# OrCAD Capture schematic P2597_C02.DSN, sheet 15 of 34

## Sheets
15 19_ON OFF CONTROLLER: size Custom
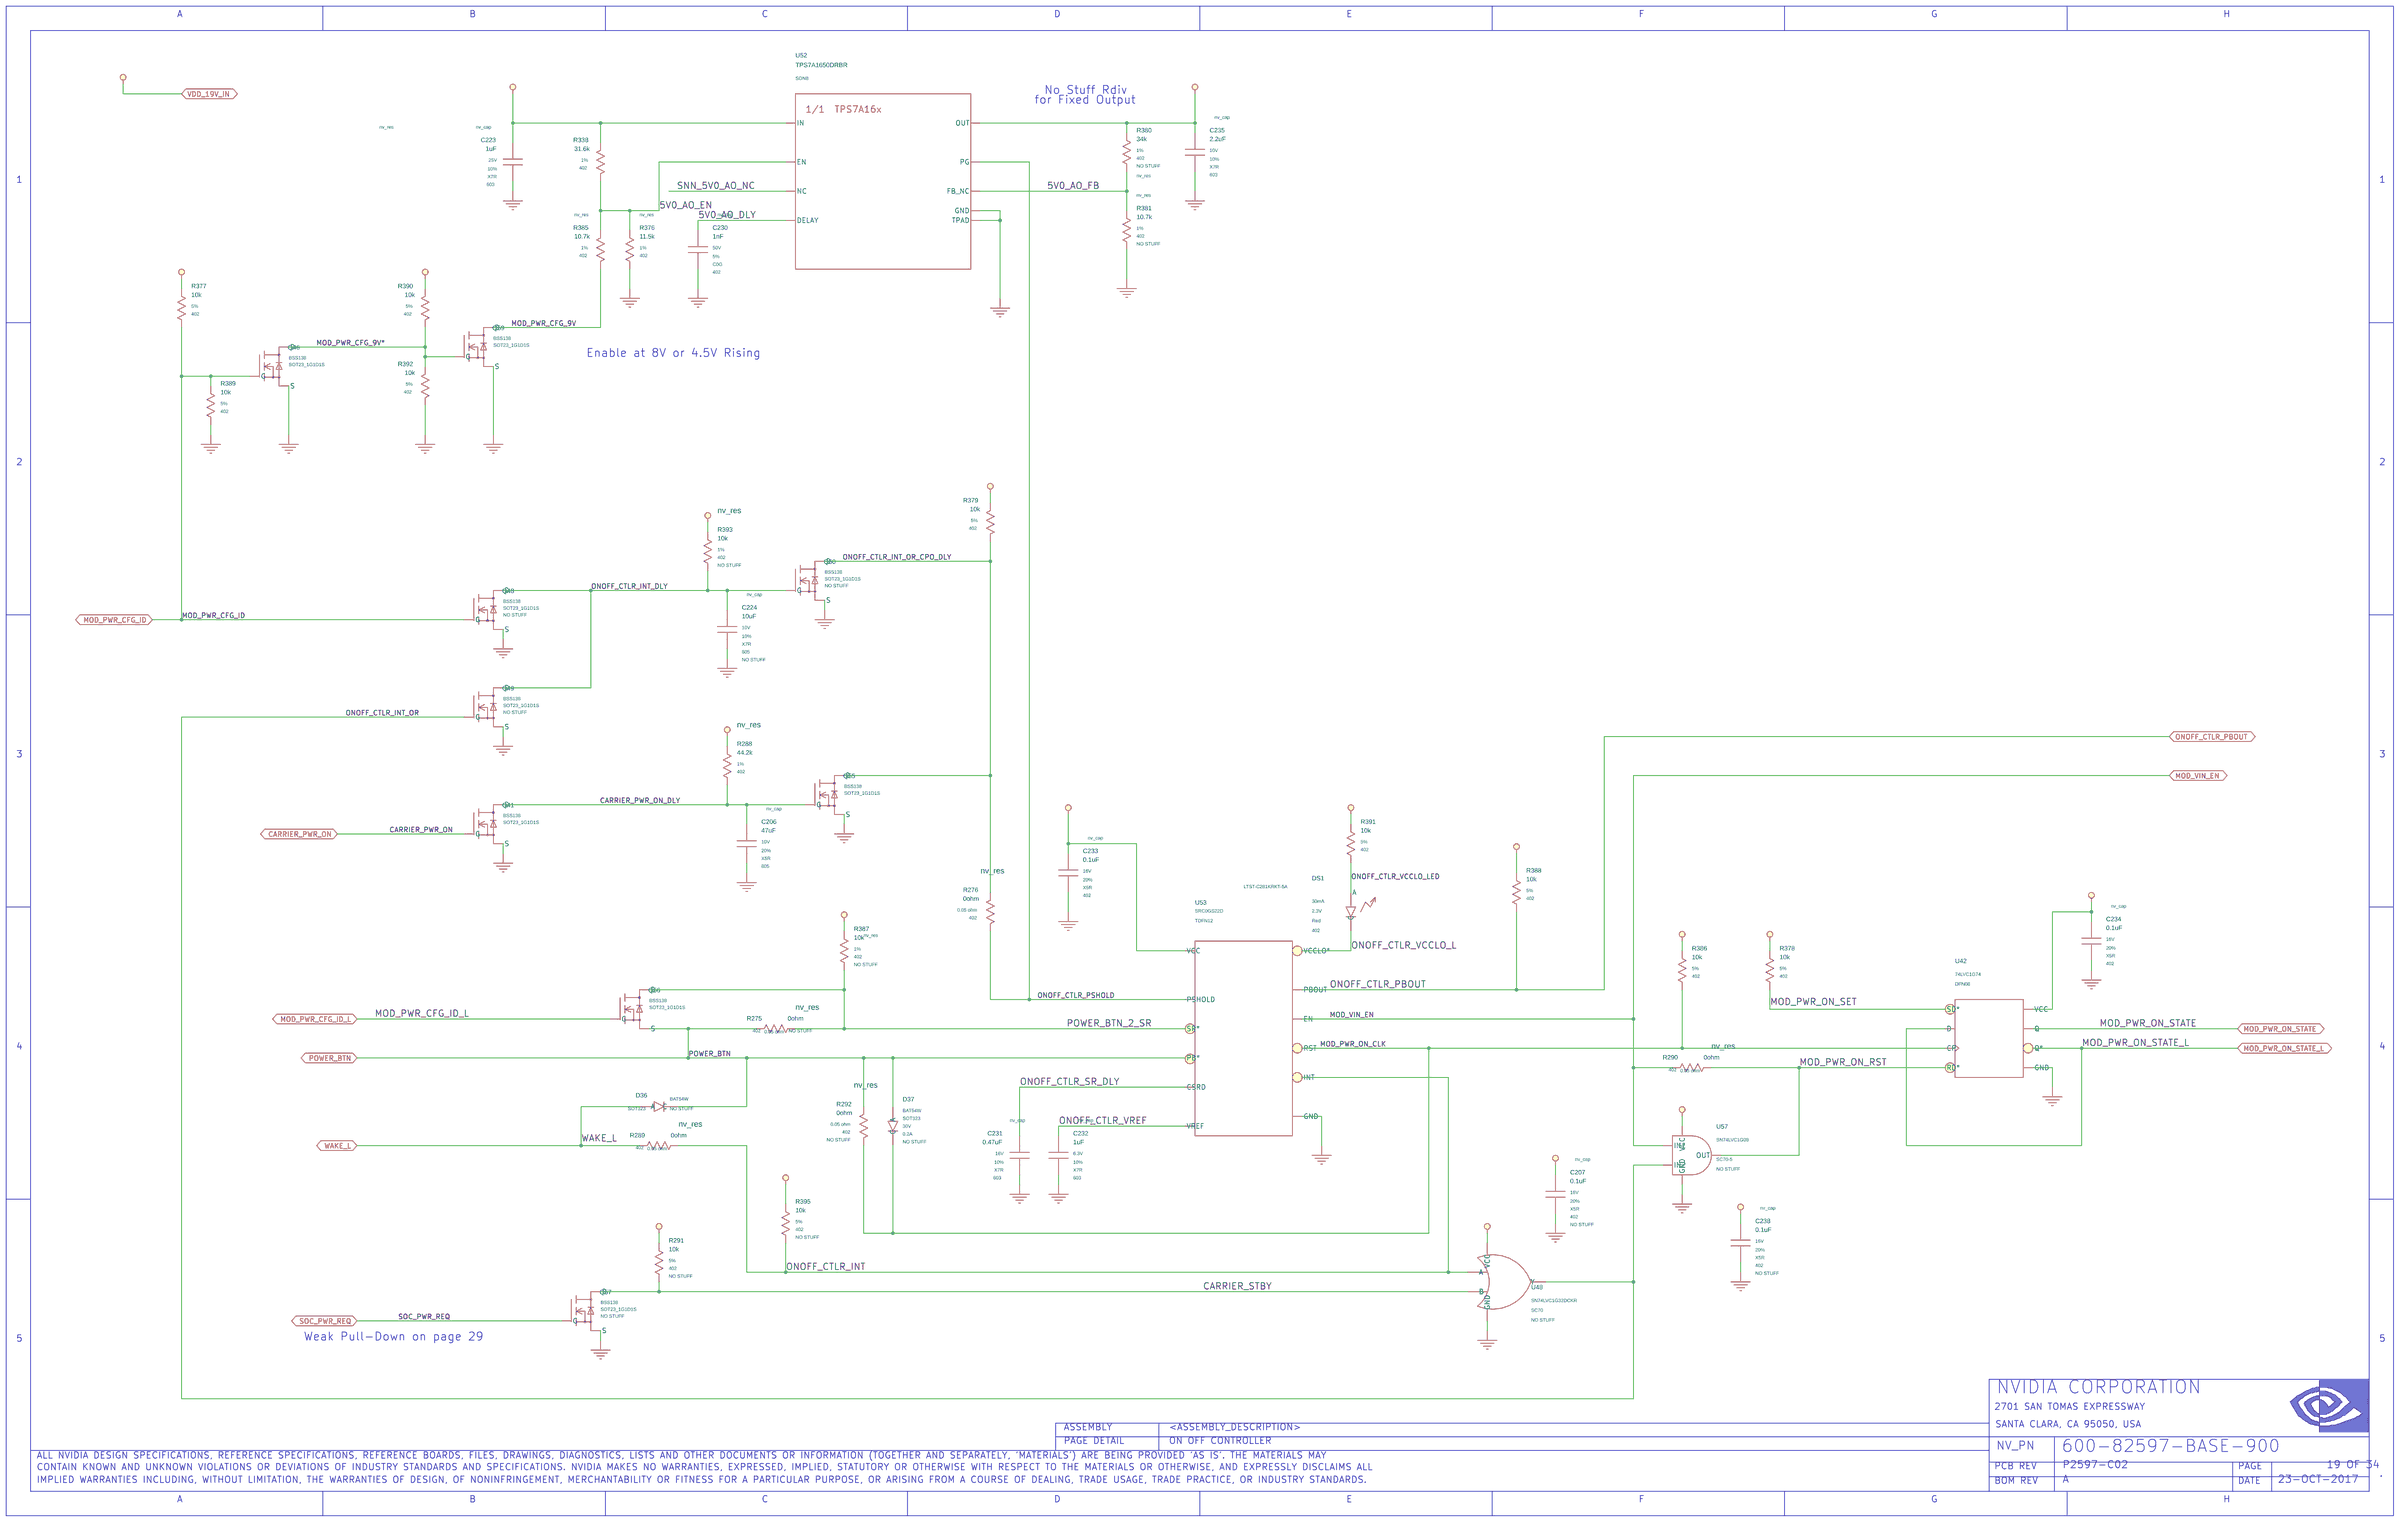
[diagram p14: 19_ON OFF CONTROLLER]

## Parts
C206  47uF  [805]
C207  0.1uF  [402]
C223  1uF  [603]
C224  10uF  [805]
C230  1nF  [402]
C231  0.47uF  [603]
C232  1uF  [603]
C233  0.1uF  [402]
C234  0.1uF  [402]
C235  2.2uF  [603]
C238  0.1uF  [402]
D36  D  [SOT323]
D37  D  [SOT323]
DS1  LED  [LED_SMD_0402_ST]
Q41  Q_FET_N_ENH  [SOT23]
Q46  Q_FET_N_ENH  [SOT23]
Q48  Q_FET_N_ENH  [SOT23]
Q49  Q_FET_N_ENH  [SOT23]
Q55  Q_FET_N_ENH  [SOT23]
Q56  Q_FET_N_ENH  [SOT23]
Q57  Q_FET_N_ENH  [SOT23]
Q59  Q_FET_N_ENH  [SOT23]
Q60  Q_FET_N_ENH  [SOT23]
R275  0ohm  [402]
R276  0ohm  [402]
R288  44.2k  [402]
R289  0ohm  [402]
R290  0ohm  [402]
R291  10k  [402]
R292  0ohm  [402]
R338  31.6k  [402]
R376  11.5k  [402]
R377  10k  [402]
R378  10k  [402]
R379  10k  [402]
R380  34k  [402]
R381  10.7k  [402]
R385  10.7k  [402]
R386  10k  [402]
R387  10k  [402]
R388  10k  [402]
R389  10k  [402]
R390  10k  [402]
R391  10k  [402]
R392  10k  [402]
R393  10k  [402]
R395  10k  [402]
U42  U_FLIPFLOP_D  [DFN08_P050_020X010]
U48  U_OR_2IN  [SC70_5]
U52  1.2V  [SON08_030X030_T025X017]
U53  U_PB_SRC0XXX  [DFN12_P050_030X020]
U57  U_AND_2IN  [SC70_5]

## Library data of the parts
C206 = C: ASSEMBLY: ON_OFF_CTRL; CDS_LIB: discrete; CDS_PART_NAME: C_0805-47UF,X5R,20%,10V,032-0775-000; CDS_PHYS_PART_NAME: C_0805-47UF,X5R,20%,10V,032-0775-000-032-0775-000,47UF; CDS_SEC: 1; DEVICE_TYPENAME: C_0805-47UFX5R2010V032-0775-000-032-0775-00047UF; DRAWING: @P2597_C02_LIB.P2597_C02(SCH_1):PAGE19; MAT: X5R; MAX_VOLTAGE: 10V; NV_PN: 032-0775-000; PATH: I158; PHYS_PAGE: 19; ROT: 0; SEC: 1; SIGNAL_MODEL: nv_cap; TOL: 20%; VER: 1; XY: (-8350,3300)
C207 = C: ASSEMBLY: ON_OFF_CTRL_INT_OFF; CDS_LIB: discrete; CDS_PART_NAME: C_0402-0.1UF,X5R,20%,16V,032-0877-000; CDS_PHYS_PART_NAME: C_0402-0.1UF,X5R,20%,16V,032-0877-000-0.1UF,032-0877-000; CDS_SEC: 1; DEVICE_TYPENAME: C_0402-01UFX5R2016V032-0877-000-01UF032-0877-000; DRAWING: @P2597_C02_LIB.P2597_C02(SCH_1):PAGE19; MAT: X5R; MAX_VOLTAGE: 16V; NV_PN: 032-0877-000; PATH: I163; PHYS_PAGE: 19; ROT: 0; SEC: 1; SIGNAL_MODEL: nv_cap; SKU: NO STUFF; TOL: 20%; VER: 1; XY: (-4200,1500)
C223 = C: ASSEMBLY: ON_OFF_CTRL; CDS_LIB: discrete; CDS_PART_NAME: C_0603-1UF,X7R,10%,25V,032-0686-000; CDS_PHYS_PART_NAME: C_0603-1UF,X7R,10%,25V,032-0686-000-032-0686-000,1UF; CDS_SEC: 1; DEVICE_TYPENAME: C_0603-1UFX7R1025V032-0686-000-032-0686-0001UF; DRAWING: @P2597_C02_LIB.P2597_C02(SCH_1):PAGE19; MAT: X7R; MAX_VOLTAGE: 25V; NV_PN: 032-0686-000; PATH: I109; PHYS_PAGE: 19; ROT: 2; SEC: 1; SIGNAL_MODEL: nv_cap; TOL: 10%; VER: 1; XY: (-9550,6800)
C224 = C: ASSEMBLY: ON_OFF_CTRL_INT_OFF; CDS_LIB: discrete; CDS_PART_NAME: C_0805-10UF,X7R,10%,10V,032-0462-000; CDS_PHYS_PART_NAME: C_0805-10UF,X7R,10%,10V,032-0462-000-032-0462-000,10UF; CDS_SEC: 1; DEVICE_TYPENAME: C_0805-10UFX7R1010V032-0462-000-032-0462-00010UF; DRAWING: @P2597_C02_LIB.P2597_C02(SCH_1):PAGE19; MAT: X7R; MAX_VOLTAGE: 10V; NV_PN: 032-0462-000; PATH: I133; PHYS_PAGE: 19; ROT: 0; SEC: 1; SIGNAL_MODEL: nv_cap; SKU: NO STUFF; TOL: 10%; VER: 1; XY: (-8450,4400)
C230 = C: ASSEMBLY: ON_OFF_CTRL; CDS_LIB: discrete; CDS_PART_NAME: C_0402-1NF,C0G,5%,50V,035-0298-000; CDS_PHYS_PART_NAME: C_0402-1NF,C0G,5%,50V,035-0298-000-035-0298-000,1NF; CDS_SEC: 1; DEVICE_TYPENAME: C_0402-1NFC0G550V035-0298-000-035-0298-0001NF; DRAWING: @P2597_C02_LIB.P2597_C02(SCH_1):PAGE19; MAT: C0G; MAX_VOLTAGE: 50V; NV_PN: 035-0298-000; PATH: I101; PHYS_PAGE: 19; ROT: 0; SEC: 1; SIGNAL_MODEL: nv_cap; TOL: 5%; VER: 1; XY: (-8600,6350)
C231 = C: ASSEMBLY: ON_OFF_CTRL; CDS_LIB: discrete; CDS_PART_NAME: C_0603-0.47UF,X7R,10%,16V,036-0040-000; CDS_PHYS_PART_NAME: C_0603-0.47UF,X7R,10%,16V,036-0040-000-0.47UF,036-0040-000; CDS_SEC: 1; DEVICE_TYPENAME: C_0603-047UFX7R1016V036-0040-000-047UF036-0040-000; DRAWING: @P2597_C02_LIB.P2597_C02(SCH_1):PAGE19; MAT: X7R; MAX_VOLTAGE: 16V; NV_PN: 036-0040-000; PATH: I138; PHYS_PAGE: 19; ROT: 2; SEC: 1; SIGNAL_MODEL: nv_cap; TOL: 10%; VER: 1; XY: (-6950,1700)
C232 = C: ASSEMBLY: ON_OFF_CTRL; CDS_LIB: discrete; CDS_PART_NAME: C_0603-1UF,X7R,10%,6.3V,036-0027-000; CDS_PHYS_PART_NAME: C_0603-1UF,X7R,10%,6.3V,036-0027-000-036-0027-000,1UF; CDS_SEC: 1; DEVICE_TYPENAME: C_0603-1UFX7R1063V036-0027-000-036-0027-0001UF; DRAWING: @P2597_C02_LIB.P2597_C02(SCH_1):PAGE19; MAT: X7R; MAX_VOLTAGE: 6.3V; NV_PN: 036-0027-000; PATH: I103; PHYS_PAGE: 19; ROT: 0; SEC: 1; SIGNAL_MODEL: nv_cap; TOL: 10%; VER: 1; XY: (-6750,1700)
C233 = C: ASSEMBLY: ON_OFF_CTRL; CDS_LIB: discrete; CDS_PART_NAME: C_0402-0.1UF,X5R,20%,16V,032-0877-000; CDS_PHYS_PART_NAME: C_0402-0.1UF,X5R,20%,16V,032-0877-000-0.1UF,032-0877-000; CDS_SEC: 1; DEVICE_TYPENAME: C_0402-01UFX5R2016V032-0877-000-01UF032-0877-000; DRAWING: @P2597_C02_LIB.P2597_C02(SCH_1):PAGE19; MAT: X5R; MAX_VOLTAGE: 16V; NV_PN: 032-0877-000; PATH: I95; PHYS_PAGE: 19; ROT: 0; SEC: 1; SIGNAL_MODEL: nv_cap; TOL: 20%; VER: 1; XY: (-6700,3150)
C234 = C: ASSEMBLY: ON_OFF_CTRL; CDS_LIB: discrete; CDS_PART_NAME: C_0402-0.1UF,X5R,20%,16V,032-0877-000; CDS_PHYS_PART_NAME: C_0402-0.1UF,X5R,20%,16V,032-0877-000-0.1UF,032-0877-000; CDS_SEC: 1; DEVICE_TYPENAME: C_0402-01UFX5R2016V032-0877-000-01UF032-0877-000; DRAWING: @P2597_C02_LIB.P2597_C02(SCH_1):PAGE19; MAT: X5R; MAX_VOLTAGE: 16V; NV_PN: 032-0877-000; PATH: I48; PHYS_PAGE: 19; ROT: 0; SEC: 1; SIGNAL_MODEL: nv_cap; TOL: 20%; VER: 1; XY: (-1450,2800)
C235 = C: ASSEMBLY: ON_OFF_CTRL; CDS_LIB: discrete; CDS_PART_NAME: C_0603-2.2UF,X7R,10%,10V,036-0219-000; CDS_PHYS_PART_NAME: C_0603-2.2UF,X7R,10%,10V,036-0219-000-036-0219-000,2.2UF; CDS_SEC: 1; DEVICE_TYPENAME: C_0603-22UFX7R1010V036-0219-000-036-0219-00022UF; DRAWING: @P2597_C02_LIB.P2597_C02(SCH_1):PAGE19; MAT: X7R; MAX_VOLTAGE: 10V; NV_PN: 036-0219-000; PATH: I67; PHYS_PAGE: 19; ROT: 0; SEC: 1; SIGNAL_MODEL: nv_cap; TOL: 10%; VER: 1; XY: (-6050,6850)
C238 = C: ASSEMBLY: ON_OFF_CTRL_INT_OFF; CDS_LIB: discrete; CDS_PART_NAME: C_0402-0.1UF,X5R,20%,16V,032-0877-000; CDS_PHYS_PART_NAME: C_0402-0.1UF,X5R,20%,16V,032-0877-000-0.1UF,032-0877-000; CDS_SEC: 1; DEVICE_TYPENAME: C_0402-01UFX5R2016V032-0877-000-01UF032-0877-000; DRAWING: @P2597_C02_LIB.P2597_C02(SCH_1):PAGE19; MAT: X5R; MAX_VOLTAGE: 16V; NV_PN: 032-0877-000; PATH: I88; PHYS_PAGE: 19; ROT: 0; SEC: 1; SIGNAL_MODEL: nv_cap; SKU: NO STUFF; TOL: 20%; VER: 1; XY: (-3250,1250)
D36 = D: ASSEMBLY: ON_OFF_CTRL_PB2WAKE; CDS_LIB: discrete; CDS_PART_NAME: D_SOT323-BAT54W,SINGLE,30V,0.6A,1V@0.1A,0.2A,090-0106-000; CDS_PHYS_PART_NAME: D_SOT323-BAT54W,SINGLE,30V,0.6A,1V@0.1A,0.2A,090-0106-000-090-0106-000; CDS_SEC: 1; CONFIGURATION: Single; CONTINUOUS_CURRENT: 0.2A; DEVICE_TYPENAME: D_SOT323-BAT54WSINGLE30V06A1V01A02A090-0106-000-090-0106-000; DRAWING: @P2597_C02_LIB.P2597_C02(SCH_1):PAGE19; FORWARD_VOLTAGE: 1V@0.1A; MAX_CURRENT: 0.6A; MAX_VOLTAGE: 30V; NV_NAME: BAT54W; NV_PN: 090-0106-000; PATH: I174; PHYS_PAGE: 19; ROT: 0; SEC: 1; SKU: NO STUFF; VER: 3; XY: (-8800,1950)
D37 = D#1: ASSEMBLY: ON_OFF_CTRL_RST2PB; CDS_LIB: discrete; CDS_PART_NAME: D_SOT323-BAT54W,SINGLE,30V,0.6A,1V@0.1A,0.2A,090-0106-000; CDS_PHYS_PART_NAME: D_SOT323-BAT54W,SINGLE,30V,0.6A,1V@0.1A,0.2A,090-0106-000-090-0106-000; CDS_SEC: 1; CONFIGURATION: Single; CONTINUOUS_CURRENT: 0.2A; DEVICE_TYPENAME: D_SOT323-BAT54WSINGLE30V06A1V01A02A090-0106-000-090-0106-000; DRAWING: @P2597_C02_LIB.P2597_C02(SCH_1):PAGE19; FORWARD_VOLTAGE: 1V@0.1A; MAX_CURRENT: 0.6A; MAX_VOLTAGE: 30V; NV_NAME: BAT54W; NV_PN: 090-0106-000; PATH: I184; PHYS_PAGE: 19; ROT: 0; SEC: 1; SKU: NO STUFF; VER: 1; XY: (-7600,1850)
DS1 = LED: ASSEMBLY: ON_OFF_CTRL_VCCLO_LED; CDS_LIB: discrete; CDS_PART_NAME: LED_0402-LTST-C281KRKT-5A,5V,80MA,2.3V,30MA,RED,092-0090-000; CDS_PHYS_PART_NAME: LED_0402-LTST-C281KRKT-5A,5V,80MA,2.3V,30MA,RED,092-0090-000-092-0090-000; CDS_SEC: 1; CONTINUOUS_CURRENT: 30mA; DEVICE_TYPENAME: LED_0402-LTST-C281KRKT-5A5V80MA23V30MARED092-0090-000-092-0090-000; DRAWING: @P2597_C02_LIB.P2597_C02(SCH_1):PAGE19; FORWARD_VOLTAGE: 2.3V; MAX_CURRENT: 80mA; MAX_VOLTAGE: 5V; NV_COLOR: Red; NV_NAME: LTST-C281KRKT-5A; NV_PN: 092-0090-000; PACK_TYPE: 402; PATH: I93; PHYS_PAGE: 19; ROT: 0; SEC: 1; VER: 1; XY: (-5250,2950)
Q41 = Q_FET_N_ENH#2: ASSEMBLY: ON_OFF_CTRL; CDS_LIB: discrete; CDS_PART_NAME: Q_FET_N_ENH_SOT23_1G1D1S-BSS138,50V,3500MOHM@10V / 3500MOHM@4.5V / 3500MOHM@2.5V,0.2A,0.2A,20V,0.3W,[ ]@10V / [ ]@4.5V / [ ]@2A; CDS_PHYS_PART_NAME: Q_FET_N_ENH_SOT23_1G1D1S-BSS138,50V,3500MOHM@10V / 3500MOHM@4.5V / 3500MOHM@2.5V,0.2A,0.2A,20V,0.3W,[ ]@10V / [ ]@4.5V / [ ]@2B; CDS_SEC: 1; CONTINUOUS_CURRENT: 0.2A; CaptureCellPackProp: Q_FET_N_ENH__sym_2##2; DEVICE_TYPENAME: Q_FET_N_ENH_SOT23_1G1D1S-BSS13850V3500MOHM10V3500MOHM45V3500MOHM25V02A02A20V03W10V45V2B; DRAWING: @P2597_C02_LIB.P2597_C02(SCH_1):PAGE19; MAX_CURRENT: 0.2A; MAX_VOLTAGE: 50V; MAX_WATTAGE: 0.3W; NV_NAME: BSS138; NV_PN: 300-0156-000; PACK_TYPE: SOT23_1G1D1S; PATH: I143; PHYS_PAGE: 19; Q_G: [ ]@10V / [ ]@4.5V / [ ]@2.5V; ROT: 0; R_DS_ON: 3500mohm@10V / 3500mohm@4.5V / 3500mohm@2.5V; SEC: 1; VER: 2; V_BE_GS: 20V; XY: (-9700,3400)
Q46 = Q_FET_N_ENH#2: ASSEMBLY: ON_OFF_CTRL; CDS_LIB: discrete; CDS_PART_NAME: Q_FET_N_ENH_SOT23_1G1D1S-BSS138,50V,3500MOHM@10V / 3500MOHM@4.5V / 3500MOHM@2.5V,0.2A,0.2A,20V,0.3W,[ ]@10V / [ ]@4.5V / [ ]@2A; CDS_PHYS_PART_NAME: Q_FET_N_ENH_SOT23_1G1D1S-BSS138,50V,3500MOHM@10V / 3500MOHM@4.5V / 3500MOHM@2.5V,0.2A,0.2A,20V,0.3W,[ ]@10V / [ ]@4.5V / [ ]@2B; CDS_SEC: 1; CONTINUOUS_CURRENT: 0.2A; CaptureCellPackProp: Q_FET_N_ENH__sym_2##2; DEVICE_TYPENAME: Q_FET_N_ENH_SOT23_1G1D1S-BSS13850V3500MOHM10V3500MOHM45V3500MOHM25V02A02A20V03W10V45V2B; DRAWING: @P2597_C02_LIB.P2597_C02(SCH_1):PAGE19; MAX_CURRENT: 0.2A; MAX_VOLTAGE: 50V; MAX_WATTAGE: 0.3W; NV_NAME: BSS138; NV_PN: 300-0156-000; PACK_TYPE: SOT23_1G1D1S; PATH: I121; PHYS_PAGE: 19; Q_G: [ ]@10V / [ ]@4.5V / [ ]@2.5V; ROT: 0; R_DS_ON: 3500mohm@10V / 3500mohm@4.5V / 3500mohm@2.5V; SEC: 1; VER: 2; V_BE_GS: 20V; XY: (-10800,5750)
Q48 = Q_FET_N_ENH#2: ASSEMBLY: ON_OFF_CTRL_INT_OFF; CDS_LIB: discrete; CDS_PART_NAME: Q_FET_N_ENH_SOT23_1G1D1S-BSS138,50V,3500MOHM@10V / 3500MOHM@4.5V / 3500MOHM@2.5V,0.2A,0.2A,20V,0.3W,[ ]@10V / [ ]@4.5V / [ ]@2A; CDS_PHYS_PART_NAME: Q_FET_N_ENH_SOT23_1G1D1S-BSS138,50V,3500MOHM@10V / 3500MOHM@4.5V / 3500MOHM@2.5V,0.2A,0.2A,20V,0.3W,[ ]@10V / [ ]@4.5V / [ ]@2B; CDS_SEC: 1; CONTINUOUS_CURRENT: 0.2A; CaptureCellPackProp: Q_FET_N_ENH__sym_2##2; DEVICE_TYPENAME: Q_FET_N_ENH_SOT23_1G1D1S-BSS13850V3500MOHM10V3500MOHM45V3500MOHM25V02A02A20V03W10V45V2B; DRAWING: @P2597_C02_LIB.P2597_C02(SCH_1):PAGE19; MAX_CURRENT: 0.2A; MAX_VOLTAGE: 50V; MAX_WATTAGE: 0.3W; NV_NAME: BSS138; NV_PN: 300-0156-000; PACK_TYPE: SOT23_1G1D1S; PATH: I141; PHYS_PAGE: 19; Q_G: [ ]@10V / [ ]@4.5V / [ ]@2.5V; ROT: 0; R_DS_ON: 3500mohm@10V / 3500mohm@4.5V / 3500mohm@2.5V; SEC: 1; SKU: NO STUFF; VER: 2; V_BE_GS: 20V; XY: (-9700,4500)
Q49 = Q_FET_N_ENH#2: ASSEMBLY: ON_OFF_CTRL_INT_OFF; CDS_LIB: discrete; CDS_PART_NAME: Q_FET_N_ENH_SOT23_1G1D1S-BSS138,50V,3500MOHM@10V / 3500MOHM@4.5V / 3500MOHM@2.5V,0.2A,0.2A,20V,0.3W,[ ]@10V / [ ]@4.5V / [ ]@2A; CDS_PHYS_PART_NAME: Q_FET_N_ENH_SOT23_1G1D1S-BSS138,50V,3500MOHM@10V / 3500MOHM@4.5V / 3500MOHM@2.5V,0.2A,0.2A,20V,0.3W,[ ]@10V / [ ]@4.5V / [ ]@2B; CDS_SEC: 1; CONTINUOUS_CURRENT: 0.2A; CaptureCellPackProp: Q_FET_N_ENH__sym_2##2; DEVICE_TYPENAME: Q_FET_N_ENH_SOT23_1G1D1S-BSS13850V3500MOHM10V3500MOHM45V3500MOHM25V02A02A20V03W10V45V2B; DRAWING: @P2597_C02_LIB.P2597_C02(SCH_1):PAGE19; MAX_CURRENT: 0.2A; MAX_VOLTAGE: 50V; MAX_WATTAGE: 0.3W; NV_NAME: BSS138; NV_PN: 300-0156-000; PACK_TYPE: SOT23_1G1D1S; PATH: I144; PHYS_PAGE: 19; Q_G: [ ]@10V / [ ]@4.5V / [ ]@2.5V; ROT: 0; R_DS_ON: 3500mohm@10V / 3500mohm@4.5V / 3500mohm@2.5V; SEC: 1; SKU: NO STUFF; VER: 2; V_BE_GS: 20V; XY: (-9700,4000)
Q55 = Q_FET_N_ENH#2: ASSEMBLY: ON_OFF_CTRL; CDS_LIB: discrete; CDS_PART_NAME: Q_FET_N_ENH_SOT23_1G1D1S-BSS138,50V,3500MOHM@10V / 3500MOHM@4.5V / 3500MOHM@2.5V,0.2A,0.2A,20V,0.3W,[ ]@10V / [ ]@4.5V / [ ]@2A; CDS_PHYS_PART_NAME: Q_FET_N_ENH_SOT23_1G1D1S-BSS138,50V,3500MOHM@10V / 3500MOHM@4.5V / 3500MOHM@2.5V,0.2A,0.2A,20V,0.3W,[ ]@10V / [ ]@4.5V / [ ]@2B; CDS_SEC: 1; CONTINUOUS_CURRENT: 0.2A; CaptureCellPackProp: Q_FET_N_ENH__sym_2##2; DEVICE_TYPENAME: Q_FET_N_ENH_SOT23_1G1D1S-BSS13850V3500MOHM10V3500MOHM45V3500MOHM25V02A02A20V03W10V45V2B; DRAWING: @P2597_C02_LIB.P2597_C02(SCH_1):PAGE19; MAX_CURRENT: 0.2A; MAX_VOLTAGE: 50V; MAX_WATTAGE: 0.3W; NV_NAME: BSS138; NV_PN: 300-0156-000; PACK_TYPE: SOT23_1G1D1S; PATH: I161; PHYS_PAGE: 19; Q_G: [ ]@10V / [ ]@4.5V / [ ]@2.5V; ROT: 0; R_DS_ON: 3500mohm@10V / 3500mohm@4.5V / 3500mohm@2.5V; SEC: 1; VER: 2; V_BE_GS: 20V; XY: (-7950,3550)
Q56 = Q_FET_N_ENH#2: ASSEMBLY: ON_OFF_CTRL_PB2SR_SMPL; CDS_LIB: discrete; CDS_PART_NAME: Q_FET_N_ENH_SOT23_1G1D1S-BSS138,50V,3500MOHM@10V / 3500MOHM@4.5V / 3500MOHM@2.5V,0.2A,0.2A,20V,0.3W,[ ]@10V / [ ]@4.5V / [ ]@2A; CDS_PHYS_PART_NAME: Q_FET_N_ENH_SOT23_1G1D1S-BSS138,50V,3500MOHM@10V / 3500MOHM@4.5V / 3500MOHM@2.5V,0.2A,0.2A,20V,0.3W,[ ]@10V / [ ]@4.5V / [ ]@2B; CDS_SEC: 1; CONTINUOUS_CURRENT: 0.2A; CaptureCellPackProp: Q_FET_N_ENH__sym_2##2; DEVICE_TYPENAME: Q_FET_N_ENH_SOT23_1G1D1S-BSS13850V3500MOHM10V3500MOHM45V3500MOHM25V02A02A20V03W10V45V2B; DRAWING: @P2597_C02_LIB.P2597_C02(SCH_1):PAGE19; MAX_CURRENT: 0.2A; MAX_VOLTAGE: 50V; MAX_WATTAGE: 0.3W; NV_NAME: BSS138; NV_PN: 300-0156-000; PACK_TYPE: SOT23_1G1D1S; PATH: I176; PHYS_PAGE: 19; Q_G: [ ]@10V / [ ]@4.5V / [ ]@2.5V; ROT: 0; R_DS_ON: 3500mohm@10V / 3500mohm@4.5V / 3500mohm@2.5V; SEC: 1; VER: 2; V_BE_GS: 20V; XY: (-8950,2450)
Q57 = Q_FET_N_ENH#2: ASSEMBLY: ON_OFF_CTRL_INT_OFF; CDS_LIB: discrete; CDS_PART_NAME: Q_FET_N_ENH_SOT23_1G1D1S-BSS138,50V,3500MOHM@10V / 3500MOHM@4.5V / 3500MOHM@2.5V,0.2A,0.2A,20V,0.3W,[ ]@10V / [ ]@4.5V / [ ]@2A; CDS_PHYS_PART_NAME: Q_FET_N_ENH_SOT23_1G1D1S-BSS138,50V,3500MOHM@10V / 3500MOHM@4.5V / 3500MOHM@2.5V,0.2A,0.2A,20V,0.3W,[ ]@10V / [ ]@4.5V / [ ]@2B; CDS_SEC: 1; CONTINUOUS_CURRENT: 0.2A; CaptureCellPackProp: Q_FET_N_ENH__sym_2##2; DEVICE_TYPENAME: Q_FET_N_ENH_SOT23_1G1D1S-BSS13850V3500MOHM10V3500MOHM45V3500MOHM25V02A02A20V03W10V45V2B; DRAWING: @P2597_C02_LIB.P2597_C02(SCH_1):PAGE19; MAX_CURRENT: 0.2A; MAX_VOLTAGE: 50V; MAX_WATTAGE: 0.3W; NV_NAME: BSS138; NV_PN: 300-0156-000; PACK_TYPE: SOT23_1G1D1S; PATH: I183; PHYS_PAGE: 19; Q_G: [ ]@10V / [ ]@4.5V / [ ]@2.5V; ROT: 0; R_DS_ON: 3500mohm@10V / 3500mohm@4.5V / 3500mohm@2.5V; SEC: 1; SKU: NO STUFF; VER: 2; V_BE_GS: 20V; XY: (-9200,900)
Q59 = Q_FET_N_ENH#2: ASSEMBLY: ON_OFF_CTRL; CDS_LIB: discrete; CDS_PART_NAME: Q_FET_N_ENH_SOT23_1G1D1S-BSS138,50V,3500MOHM@10V / 3500MOHM@4.5V / 3500MOHM@2.5V,0.2A,0.2A,20V,0.3W,[ ]@10V / [ ]@4.5V / [ ]@2A; CDS_PHYS_PART_NAME: Q_FET_N_ENH_SOT23_1G1D1S-BSS138,50V,3500MOHM@10V / 3500MOHM@4.5V / 3500MOHM@2.5V,0.2A,0.2A,20V,0.3W,[ ]@10V / [ ]@4.5V / [ ]@2B; CDS_SEC: 1; CONTINUOUS_CURRENT: 0.2A; CaptureCellPackProp: Q_FET_N_ENH__sym_2##2; DEVICE_TYPENAME: Q_FET_N_ENH_SOT23_1G1D1S-BSS13850V3500MOHM10V3500MOHM45V3500MOHM25V02A02A20V03W10V45V2B; DRAWING: @P2597_C02_LIB.P2597_C02(SCH_1):PAGE19; MAX_CURRENT: 0.2A; MAX_VOLTAGE: 50V; MAX_WATTAGE: 0.3W; NV_NAME: BSS138; NV_PN: 300-0156-000; PACK_TYPE: SOT23_1G1D1S; PATH: I115; PHYS_PAGE: 19; Q_G: [ ]@10V / [ ]@4.5V / [ ]@2.5V; ROT: 0; R_DS_ON: 3500mohm@10V / 3500mohm@4.5V / 3500mohm@2.5V; SEC: 1; VER: 2; V_BE_GS: 20V; XY: (-9750,5850)
Q60 = Q_FET_N_ENH#2: ASSEMBLY: ON_OFF_CTRL_INT_OFF; CDS_LIB: discrete; CDS_PART_NAME: Q_FET_N_ENH_SOT23_1G1D1S-BSS138,50V,3500MOHM@10V / 3500MOHM@4.5V / 3500MOHM@2.5V,0.2A,0.2A,20V,0.3W,[ ]@10V / [ ]@4.5V / [ ]@2A; CDS_PHYS_PART_NAME: Q_FET_N_ENH_SOT23_1G1D1S-BSS138,50V,3500MOHM@10V / 3500MOHM@4.5V / 3500MOHM@2.5V,0.2A,0.2A,20V,0.3W,[ ]@10V / [ ]@4.5V / [ ]@2B; CDS_SEC: 1; CONTINUOUS_CURRENT: 0.2A; CaptureCellPackProp: Q_FET_N_ENH__sym_2##2; DEVICE_TYPENAME: Q_FET_N_ENH_SOT23_1G1D1S-BSS13850V3500MOHM10V3500MOHM45V3500MOHM25V02A02A20V03W10V45V2B; DRAWING: @P2597_C02_LIB.P2597_C02(SCH_1):PAGE19; MAX_CURRENT: 0.2A; MAX_VOLTAGE: 50V; MAX_WATTAGE: 0.3W; NV_NAME: BSS138; NV_PN: 300-0156-000; PACK_TYPE: SOT23_1G1D1S; PATH: I128; PHYS_PAGE: 19; Q_G: [ ]@10V / [ ]@4.5V / [ ]@2.5V; ROT: 0; R_DS_ON: 3500mohm@10V / 3500mohm@4.5V / 3500mohm@2.5V; SEC: 1; SKU: NO STUFF; VER: 2; V_BE_GS: 20V; XY: (-8050,4650)
R275 = R: ASSEMBLY: ON_OFF_CTRL_PB2SR_SMPL; CDS_LIB: discrete; CDS_PART_NAME: R_0402-0OHM,0.05 OHM,62.5MW,195-2655-000; CDS_PHYS_PART_NAME: R_0402-0OHM,0.05 OHM,62.5MW,195-2655-000-0OHM,195-2655-000; CDS_SEC: 1; DEVICE_TYPENAME: R_0402-0OHM005OHM625MW195-2655-000-0OHM195-2655-000; DRAWING: @P2597_C02_LIB.P2597_C02(SCH_1):PAGE19; MAX_WATTAGE: 62.5mW; NV_PN: 195-2655-000; PATH: I135; PHYS_PAGE: 19; ROT: 0; SEC: 1; SIGNAL_MODEL: nv_res; SKU: NO STUFF; TOL: 0.05 ohm; VER: 1; XY: (-8200,2350)
R276 = R#1: ASSEMBLY: ON_OFF_CTRL; CDS_LIB: discrete; CDS_PART_NAME: R_0402-0OHM,0.05 OHM,62.5MW,195-2655-000; CDS_PHYS_PART_NAME: R_0402-0OHM,0.05 OHM,62.5MW,195-2655-000-0OHM,195-2655-000; CDS_SEC: 1; CHIPS_PART_NAME: R; DEVICE_TYPENAME: R_0402-0OHM005OHM625MW195-2655-000-0OHM195-2655-000; DRAWING: @P2597_C02_LIB.P2597_C02(SCH_1):PAGE19; MAX_WATTAGE: 62.5mW; NV_PN: 195-2655-000; PATH: I126; PHYS_PAGE: 19; ROT: 2; SEC: 1; SIGNAL_MODEL: nv_res; TOL: 0.05 ohm; VER: 2; XY: (-7100,2950)
R288 = R#1: ASSEMBLY: ON_OFF_CTRL; CDS_LIB: discrete; CDS_PART_NAME: R_0402-44.2K,1 %,62.5MW,195-0315-000; CDS_PHYS_PART_NAME: R_0402-44.2K,1 %,62.5MW,195-0315-000-195-0315-000,44.2K; CDS_SEC: 1; CHIPS_PART_NAME: R; DEVICE_TYPENAME: R_0402-442K1625MW195-0315-000-195-0315-000442K; DRAWING: @P2597_C02_LIB.P2597_C02(SCH_1):PAGE19; MAX_WATTAGE: 62.5mW; NV_PN: 195-0315-000; PATH: I157; PHYS_PAGE: 19; ROT: 0; SEC: 1; SIGNAL_MODEL: nv_res; TOL: 1%; VER: 2; XY: (-8450,3700)
R289 = R: ASSEMBLY: ON_OFF_CTRL_INT2WAKE; CDS_LIB: discrete; CDS_PART_NAME: R_0402-0OHM,0.05 OHM,62.5MW,195-2655-000; CDS_PHYS_PART_NAME: R_0402-0OHM,0.05 OHM,62.5MW,195-2655-000-0OHM,195-2655-000; CDS_SEC: 1; DEVICE_TYPENAME: R_0402-0OHM005OHM625MW195-2655-000-0OHM195-2655-000; DRAWING: @P2597_C02_LIB.P2597_C02(SCH_1):PAGE19; MAX_WATTAGE: 62.5mW; NV_PN: 195-2655-000; PATH: I172; PHYS_PAGE: 19; ROT: 0; SEC: 1; SIGNAL_MODEL: nv_res; TOL: 0.05 ohm; VER: 1; XY: (-8800,1750)
R290 = R: ASSEMBLY: ON_OFF_CTRL_INT_OFF_AND_BYPASS; CDS_LIB: discrete; CDS_PART_NAME: R_0402-0OHM,0.05 OHM,62.5MW,195-2655-000; CDS_PHYS_PART_NAME: R_0402-0OHM,0.05 OHM,62.5MW,195-2655-000-0OHM,195-2655-000; CDS_SEC: 1; DEVICE_TYPENAME: R_0402-0OHM005OHM625MW195-2655-000-0OHM195-2655-000; DRAWING: @P2597_C02_LIB.P2597_C02(SCH_1):PAGE19; MAX_WATTAGE: 62.5mW; NV_PN: 195-2655-000; PATH: I181; PHYS_PAGE: 19; ROT: 0; SEC: 1; SIGNAL_MODEL: nv_res; TOL: 0.05 ohm; VER: 1; XY: (-3500,2150)
R291 = R#1: ASSEMBLY: ON_OFF_CTRL_INT_OFF; CDS_LIB: discrete; CDS_PART_NAME: R_0402-10K,5 %,62.5MW,195-0486-000; CDS_PHYS_PART_NAME: R_0402-10K,5 %,62.5MW,195-0486-000-10K,195-0486-000; CDS_SEC: 1; CHIPS_PART_NAME: R; DEVICE_TYPENAME: R_0402-10K5625MW195-0486-000-10K195-0486-000; DRAWING: @P2597_C02_LIB.P2597_C02(SCH_1):PAGE19; MAX_WATTAGE: 62.5mW; NV_PN: 195-0486-000; PATH: I182; PHYS_PAGE: 19; ROT: 0; SEC: 1; SIGNAL_MODEL: DEFAULT_RESISTOR_10000OHM_2_1; SKU: NO STUFF; TOL: 5%; VER: 2; XY: (-8800,1150)
R292 = R#1: ASSEMBLY: ON_OFF_CTRL_RST2PB; CDS_LIB: discrete; CDS_PART_NAME: R_0402-0OHM,0.05 OHM,62.5MW,195-2655-000; CDS_PHYS_PART_NAME: R_0402-0OHM,0.05 OHM,62.5MW,195-2655-000-0OHM,195-2655-000; CDS_SEC: 1; CHIPS_PART_NAME: R; DEVICE_TYPENAME: R_0402-0OHM005OHM625MW195-2655-000-0OHM195-2655-000; DRAWING: @P2597_C02_LIB.P2597_C02(SCH_1):PAGE19; MAX_WATTAGE: 62.5mW; NV_PN: 195-2655-000; PATH: I185; PHYS_PAGE: 19; ROT: 2; SEC: 1; SIGNAL_MODEL: nv_res; SKU: NO STUFF; TOL: 0.05 ohm; VER: 2; XY: (-7750,1850)
R338 = R#1: ASSEMBLY: ON_OFF_CTRL; CDS_LIB: discrete; CDS_PART_NAME: R_0402-31.6K,1 %,62.5MW,195-0245-000; CDS_PHYS_PART_NAME: R_0402-31.6K,1 %,62.5MW,195-0245-000-195-0245-000,31.6K; CDS_SEC: 1; CHIPS_PART_NAME: R; DEVICE_TYPENAME: R_0402-316K1625MW195-0245-000-195-0245-000316K; DRAWING: @P2597_C02_LIB.P2597_C02(SCH_1):PAGE19; MAX_WATTAGE: 62.5mW; NV_PN: 195-0245-000; PATH: I106; PHYS_PAGE: 19; ROT: 2; SEC: 1; SIGNAL_MODEL: nv_res; TOL: 1%; VER: 2; XY: (-9100,6800)
R376 = R#1: ASSEMBLY: ON_OFF_CTRL; CDS_LIB: discrete; CDS_PART_NAME: R_0402-11.5K,1 %,62.5MW,195-0035-000; CDS_PHYS_PART_NAME: R_0402-11.5K,1 %,62.5MW,195-0035-000-11.5K,195-0035-000; CDS_SEC: 1; CHIPS_PART_NAME: R; DEVICE_TYPENAME: R_0402-115K1625MW195-0035-000-115K195-0035-000; DRAWING: @P2597_C02_LIB.P2597_C02(SCH_1):PAGE19; MAX_WATTAGE: 62.5mW; NV_PN: 195-0035-000; PATH: I107; PHYS_PAGE: 19; ROT: 0; SEC: 1; SIGNAL_MODEL: nv_res; TOL: 1%; VER: 2; XY: (-8950,6350)
R377 = R#1: ASSEMBLY: ON_OFF_CTRL; CDS_LIB: discrete; CDS_PART_NAME: R_0402-10K,5 %,62.5MW,195-0486-000; CDS_PHYS_PART_NAME: R_0402-10K,5 %,62.5MW,195-0486-000-10K,195-0486-000; CDS_SEC: 1; CHIPS_PART_NAME: R; DEVICE_TYPENAME: R_0402-10K5625MW195-0486-000-10K195-0486-000; DRAWING: @P2597_C02_LIB.P2597_C02(SCH_1):PAGE19; MAX_WATTAGE: 62.5mW; NV_PN: 195-0486-000; PATH: I120; PHYS_PAGE: 19; ROT: 0; SEC: 1; SIGNAL_MODEL: DEFAULT_RESISTOR_10000OHM_2_1; TOL: 5%; VER: 2; XY: (-11250,6050)
R378 = R#1: ASSEMBLY: ON_OFF_CTRL; CDS_LIB: discrete; CDS_PART_NAME: R_0402-10K,5 %,62.5MW,195-0486-000; CDS_PHYS_PART_NAME: R_0402-10K,5 %,62.5MW,195-0486-000-10K,195-0486-000; CDS_SEC: 1; CHIPS_PART_NAME: R; DEVICE_TYPENAME: R_0402-10K5625MW195-0486-000-10K195-0486-000; DRAWING: @P2597_C02_LIB.P2597_C02(SCH_1):PAGE19; MAX_WATTAGE: 62.5mW; NV_PN: 195-0486-000; PATH: I78; PHYS_PAGE: 19; ROT: 0; SEC: 1; SIGNAL_MODEL: DEFAULT_RESISTOR_10000OHM_2_1; TOL: 5%; VER: 2; XY: (-3100,2650)
R379 = R#1: ASSEMBLY: ON_OFF_CTRL; CDS_LIB: discrete; CDS_PART_NAME: R_0402-10K,5 %,62.5MW,195-0486-000; CDS_PHYS_PART_NAME: R_0402-10K,5 %,62.5MW,195-0486-000-10K,195-0486-000; CDS_SEC: 1; CHIPS_PART_NAME: R; DEVICE_TYPENAME: R_0402-10K5625MW195-0486-000-10K195-0486-000; DRAWING: @P2597_C02_LIB.P2597_C02(SCH_1):PAGE19; MAX_WATTAGE: 62.5mW; NV_PN: 195-0486-000; PATH: I125; PHYS_PAGE: 19; ROT: 2; SEC: 1; SIGNAL_MODEL: DEFAULT_RESISTOR_10000OHM_2_1; TOL: 5%; VER: 2; XY: (-7100,4950)
R380 = R#1: ASSEMBLY: ON_OFF_CTRL_5V0AO_FB_RTOP; CDS_LIB: discrete; CDS_PART_NAME: R_0402-34K,1 %,62.5MW,195-0260-000; CDS_PHYS_PART_NAME: R_0402-34K,1 %,62.5MW,195-0260-000-195-0260-000,34K; CDS_SEC: 1; CHIPS_PART_NAME: R; DEVICE_TYPENAME: R_0402-34K1625MW195-0260-000-195-0260-00034K; DRAWING: @P2597_C02_LIB.P2597_C02(SCH_1):PAGE19; MAX_WATTAGE: 62.5mW; NV_PN: 195-0260-000; PATH: I69; PHYS_PAGE: 19; ROT: 0; SEC: 1; SIGNAL_MODEL: nv_res; SKU: NO STUFF; TOL: 1%; VER: 2; XY: (-6400,6850)
R381 = R#1: ASSEMBLY: ON_OFF_CTRL_5V0AO_FB_RBOT; CDS_LIB: discrete; CDS_PART_NAME: R_0402-10.7K,1 %,62.5MW,195-0020-000; CDS_PHYS_PART_NAME: R_0402-10.7K,1 %,62.5MW,195-0020-000-10.7K,195-0020-000; CDS_SEC: 1; CHIPS_PART_NAME: R; DEVICE_TYPENAME: R_0402-107K1625MW195-0020-000-107K195-0020-000; DRAWING: @P2597_C02_LIB.P2597_C02(SCH_1):PAGE19; MAX_WATTAGE: 62.5mW; NV_PN: 195-0020-000; PATH: I70; PHYS_PAGE: 19; ROT: 0; SEC: 1; SIGNAL_MODEL: nv_res; SKU: NO STUFF; TOL: 1%; VER: 2; XY: (-6400,6450)
R385 = R#1: ASSEMBLY: ON_OFF_CTRL; CDS_LIB: discrete; CDS_PART_NAME: R_0402-10.7K,1 %,62.5MW,195-0020-000; CDS_PHYS_PART_NAME: R_0402-10.7K,1 %,62.5MW,195-0020-000-10.7K,195-0020-000; CDS_SEC: 1; CHIPS_PART_NAME: R; DEVICE_TYPENAME: R_0402-107K1625MW195-0020-000-107K195-0020-000; DRAWING: @P2597_C02_LIB.P2597_C02(SCH_1):PAGE19; MAX_WATTAGE: 62.5mW; NV_PN: 195-0020-000; PATH: I111; PHYS_PAGE: 19; ROT: 2; SEC: 1; SIGNAL_MODEL: nv_res; TOL: 1%; VER: 2; XY: (-9100,6350)
R386 = R#1: ASSEMBLY: ON_OFF_CTRL; CDS_LIB: discrete; CDS_PART_NAME: R_0402-10K,5 %,62.5MW,195-0486-000; CDS_PHYS_PART_NAME: R_0402-10K,5 %,62.5MW,195-0486-000-10K,195-0486-000; CDS_SEC: 1; CHIPS_PART_NAME: R; DEVICE_TYPENAME: R_0402-10K5625MW195-0486-000-10K195-0486-000; DRAWING: @P2597_C02_LIB.P2597_C02(SCH_1):PAGE19; MAX_WATTAGE: 62.5mW; NV_PN: 195-0486-000; PATH: I80; PHYS_PAGE: 19; ROT: 0; SEC: 1; SIGNAL_MODEL: DEFAULT_RESISTOR_10000OHM_2_1; TOL: 5%; VER: 2; XY: (-3550,2650)
R387 = R#1: ASSEMBLY: ON_OFF_CTRL_SR_CMPLX; CDS_LIB: discrete; CDS_PART_NAME: R_0402-10K,1 %,62.5MW,195-0004-000; CDS_PHYS_PART_NAME: R_0402-10K,1 %,62.5MW,195-0004-000-10K,195-0004-000; CDS_SEC: 1; CHIPS_PART_NAME: R; DEVICE_TYPENAME: R_0402-10K1625MW195-0004-000-10K195-0004-000; DRAWING: @P2597_C02_LIB.P2597_C02(SCH_1):PAGE19; MAX_WATTAGE: 62.5mW; NV_PN: 195-0004-000; PATH: I130; PHYS_PAGE: 19; ROT: 0; SEC: 1; SIGNAL_MODEL: nv_res; SKU: NO STUFF; TOL: 1%; VER: 2; XY: (-7850,2750)
R388 = R#1: ASSEMBLY: ON_OFF_CTRL; CDS_LIB: discrete; CDS_PART_NAME: R_0402-10K,5 %,62.5MW,195-0486-000; CDS_PHYS_PART_NAME: R_0402-10K,5 %,62.5MW,195-0486-000-10K,195-0486-000; CDS_SEC: 1; CHIPS_PART_NAME: R; DEVICE_TYPENAME: R_0402-10K5625MW195-0486-000-10K195-0486-000; DRAWING: @P2597_C02_LIB.P2597_C02(SCH_1):PAGE19; MAX_WATTAGE: 62.5mW; NV_PN: 195-0486-000; PATH: I85; PHYS_PAGE: 19; ROT: 0; SEC: 1; SIGNAL_MODEL: DEFAULT_RESISTOR_10000OHM_2_1; TOL: 5%; VER: 2; XY: (-4400,3050)
R389 = R#1: ASSEMBLY: ON_OFF_CTRL; CDS_LIB: discrete; CDS_PART_NAME: R_0402-10K,5 %,62.5MW,195-0486-000; CDS_PHYS_PART_NAME: R_0402-10K,5 %,62.5MW,195-0486-000-10K,195-0486-000; CDS_SEC: 1; CHIPS_PART_NAME: R; DEVICE_TYPENAME: R_0402-10K5625MW195-0486-000-10K195-0486-000; DRAWING: @P2597_C02_LIB.P2597_C02(SCH_1):PAGE19; MAX_WATTAGE: 62.5mW; NV_PN: 195-0486-000; PATH: I122; PHYS_PAGE: 19; ROT: 0; SEC: 1; SIGNAL_MODEL: DEFAULT_RESISTOR_10000OHM_2_1; TOL: 5%; VER: 2; XY: (-11100,5550)
R390 = R#1: ASSEMBLY: ON_OFF_CTRL; CDS_LIB: discrete; CDS_PART_NAME: R_0402-10K,5 %,62.5MW,195-0486-000; CDS_PHYS_PART_NAME: R_0402-10K,5 %,62.5MW,195-0486-000-10K,195-0486-000; CDS_SEC: 1; CHIPS_PART_NAME: R; DEVICE_TYPENAME: R_0402-10K5625MW195-0486-000-10K195-0486-000; DRAWING: @P2597_C02_LIB.P2597_C02(SCH_1):PAGE19; MAX_WATTAGE: 62.5mW; NV_PN: 195-0486-000; PATH: I114; PHYS_PAGE: 19; ROT: 2; SEC: 1; SIGNAL_MODEL: DEFAULT_RESISTOR_10000OHM_2_1; TOL: 5%; VER: 2; XY: (-10000,6050)
R391 = R#1: ASSEMBLY: ON_OFF_CTRL_VCCLO_PU; CDS_LIB: discrete; CDS_PART_NAME: R_0402-10K,5 %,62.5MW,195-0486-000; CDS_PHYS_PART_NAME: R_0402-10K,5 %,62.5MW,195-0486-000-10K,195-0486-000; CDS_SEC: 1; CHIPS_PART_NAME: R; DEVICE_TYPENAME: R_0402-10K5625MW195-0486-000-10K195-0486-000; DRAWING: @P2597_C02_LIB.P2597_C02(SCH_1):PAGE19; MAX_WATTAGE: 62.5mW; NV_PN: 195-0486-000; PATH: I92; PHYS_PAGE: 19; ROT: 0; SEC: 1; SIGNAL_MODEL: DEFAULT_RESISTOR_10000OHM_2_1; TOL: 5%; VER: 2; XY: (-5250,3300)
R392 = R#1: ASSEMBLY: ON_OFF_CTRL; CDS_LIB: discrete; CDS_PART_NAME: R_0402-10K,5 %,62.5MW,195-0486-000; CDS_PHYS_PART_NAME: R_0402-10K,5 %,62.5MW,195-0486-000-10K,195-0486-000; CDS_SEC: 1; CHIPS_PART_NAME: R; DEVICE_TYPENAME: R_0402-10K5625MW195-0486-000-10K195-0486-000; DRAWING: @P2597_C02_LIB.P2597_C02(SCH_1):PAGE19; MAX_WATTAGE: 62.5mW; NV_PN: 195-0486-000; PATH: I116; PHYS_PAGE: 19; ROT: 2; SEC: 1; SIGNAL_MODEL: DEFAULT_RESISTOR_10000OHM_2_1; TOL: 5%; VER: 2; XY: (-10000,5650)
R393 = R#1: ASSEMBLY: ON_OFF_CTRL_INT_OFF; CDS_LIB: discrete; CDS_PART_NAME: R_0402-10K,1 %,62.5MW,195-0004-000; CDS_PHYS_PART_NAME: R_0402-10K,1 %,62.5MW,195-0004-000-10K,195-0004-000; CDS_SEC: 1; CHIPS_PART_NAME: R; DEVICE_TYPENAME: R_0402-10K1625MW195-0004-000-10K195-0004-000; DRAWING: @P2597_C02_LIB.P2597_C02(SCH_1):PAGE19; MAX_WATTAGE: 62.5mW; NV_PN: 195-0004-000; PATH: I132; PHYS_PAGE: 19; ROT: 0; SEC: 1; SIGNAL_MODEL: nv_res; SKU: NO STUFF; TOL: 1%; VER: 2; XY: (-8550,4800)
R395 = R#1: ASSEMBLY: ON_OFF_CTRL_INT_PU; CDS_LIB: discrete; CDS_PART_NAME: R_0402-10K,5 %,62.5MW,195-0486-000; CDS_PHYS_PART_NAME: R_0402-10K,5 %,62.5MW,195-0486-000-10K,195-0486-000; CDS_SEC: 1; CHIPS_PART_NAME: R; DEVICE_TYPENAME: R_0402-10K5625MW195-0486-000-10K195-0486-000; DRAWING: @P2597_C02_LIB.P2597_C02(SCH_1):PAGE19; MAX_WATTAGE: 62.5mW; NV_PN: 195-0486-000; PATH: I98; PHYS_PAGE: 19; ROT: 0; SEC: 1; SIGNAL_MODEL: DEFAULT_RESISTOR_10000OHM_2_1; SKU: NO STUFF; TOL: 5%; VER: 2; XY: (-8150,1350)
U42 = U_FLIPFLOP_D: ASSEMBLY: ON_OFF_CTRL; CDS_LIB: logic; CDS_PART_NAME: U_FLIPFLOP_D_DFN08-74LVC1G74,LOGIC - D-TYPE FLIP FLOP WITH PRESET/CLEAR,115-0967-000; CDS_PHYS_PART_NAME: U_FLIPFLOP_D_DFN08-74LVC1G74,LOGIC - D-TYPE FLIP FLOP WITH PRESET/CLEAR,115-0967-000-115-0967-000; CDS_SEC: 1; DEVICE_TYPENAME: U_FLIPFLOP_D_DFN08-74LVC1G74LOGIC-D-TYPEFLIPFLOPWITHPRESETCLEAR115-0967-000-115-0967-000; DRAWING: @P2597_C02_LIB.P2597_C02(SCH_1):PAGE19; FUNCTION: Logic - D-Type Flip Flop with Preset/Clear; NV_NAME: 74LVC1G74; NV_PN: 115-0967-000; PACK_TYPE: DFN08; PATH: I50; PHYS_PAGE: 19; ROT: 0; SEC: 1; SEC_TYPE: DFN08; VER: 1; XY: (-2000,2300)
U48 = U_OR_2IN: ASSEMBLY: ON_OFF_CTRL_INT_OFF; CDS_LIB: logic; CDS_PART_NAME: U_OR_2IN_SC70-SN74LVC1G32DCKR,GATES - OR - 2 INPUT,115-1426-000; CDS_PHYS_PART_NAME: U_OR_2IN_SC70-SN74LVC1G32DCKR,GATES - OR - 2 INPUT,115-1426-000-115-1426-000; CDS_SEC: 1; DEVICE_TYPENAME: U_OR_2IN_SC70-SN74LVC1G32DCKRGATES-OR-2INPUT115-1426-000-115-1426-000; DRAWING: @P2597_C02_LIB.P2597_C02(SCH_1):PAGE19; FUNCTION: Gates - OR - 2 input; NV_NAME: SN74LVC1G32DCKR; NV_PN: 115-1426-000; PACK_TYPE: SC70; PATH: I167; PHYS_PAGE: 19; ROT: 0; SEC: 1; SKU: NO STUFF; VER: 1; XY: (-4450,1050)
U52 = U_VREG_TPS7A16X: ASSEMBLY: ON_OFF_CTRL; CDS_LIB: power_supply; CDS_PART_NAME: U_VREG_TPS7A16X_SON8-TPS7A1650DRBR,LOW DROP OUT/FIXED,0.5V@0.1A,5V..5V,2%,1.2V,60V,0.1A,1W,315-0988-000; CDS_PHYS_PART_NAME: U_VREG_TPS7A16X_SON8-TPS7A1650DRBR,LOW DROP OUT/FIXED,0.5V@0.1A,5V..5V,2%,1.2V,60V,0.1A,1W,315-0988-000-1.2V,315-0988-000; CDS_SEC: 1; DEVICE_TYPENAME: U_VREG_TPS7A16X_SON8-TPS7A1650DRBRLOWDROPOUTFIXED05V01A5V5V212V60V01A1W315-0988-000-12V315-0988-000; DRAWING: @P2597_C02_LIB.P2597_C02(SCH_1):PAGE19; FORWARD_VOLTAGE: 0.5V@0.1A; MAX_CURRENT: 0.1A; MAX_VOLTAGE: 60V; MAX_WATTAGE: 1W; NV_NAME: TPS7A1650DRBR; NV_PN: 315-0988-000; OUTPUT_VOLTAGE: 5V..5V; PACK_TYPE: SON8; PATH: I73; PHYS_PAGE: 19; ROT: 0; SEC: 1; SEC_TYPE: SON8; TOL: 2%; TYPE: Low Drop Out/Fixed; VER: 1; XY: (-7650,6700)
U53 = U_PB_SRC0XXX: ASSEMBLY: ON_OFF_CTRL; CDS_LIB: power_supply; CDS_PART_NAME: U_PB_SRC0XXX_TDFN12-SRC0GS22D,-9999V..9999V,-9999V..9999V,9999A,SWITCH,115-2029-000; CDS_PHYS_PART_NAME: U_PB_SRC0XXX_TDFN12-SRC0GS22D,-9999V..9999V,-9999V..9999V,9999A,SWITCH,115-2029-000-115-2029-000; CDS_SEC: 1; DEVICE_TYPENAME: U_PB_SRC0XXX_TDFN12-SRC0GS22D-9999V9999V-9999V9999V9999ASWITCH115-2029-000-115-2029-000; DRAWING: @P2597_C02_LIB.P2597_C02(SCH_1):PAGE19; MAX_CURRENT: 9999A; MAX_VOLTAGE: -9999V..9999V; NV_NAME: SRC0GS22D; NV_PN: 115-2029-000; OUTPUT_VOLTAGE: -9999V..9999V; PACK_TYPE: TDFN12; PATH: I100; PHYS_PAGE: 19; ROT: 0; SEC: 1; SEC_TYPE: TDFN12; TYPE: Switch; VER: 1; XY: (-5800,2300)
U57 = U_AND_2IN: ASSEMBLY: ON_OFF_CTRL_INT_OFF; CDS_LIB: logic; CDS_PART_NAME: U_AND_2IN_SC70-5-SN74LVC1G08,GATES - AND - 2 INPUT,115-0014-000; CDS_PHYS_PART_NAME: U_AND_2IN_SC70-5-SN74LVC1G08,GATES - AND - 2 INPUT,115-0014-000-115-0014-000; CDS_SEC: 1; DEVICE_TYPENAME: U_AND_2IN_SC70-5-SN74LVC1G08GATES-AND-2INPUT115-0014-000-115-0014-000; DRAWING: @P2597_C02_LIB.P2597_C02(SCH_1):PAGE19; FUNCTION: Gates - AND - 2 input; NV_NAME: SN74LVC1G08; NV_PN: 115-0014-000; PACK_TYPE: SC70-5; PATH: I171; PHYS_PAGE: 19; ROT: 0; SEC: 1; SKU: NO STUFF; VER: 1; XY: (-3500,1700)

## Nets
5V0_AO: C207.1 C233.1 C234.1 C235.1 C238.1 R288.1 R291.1 R378.1 R379.1 R380.1 R386.1 R387.1 R388.1 R391.1 R393.1 R395.1 U42.8(VCC) U48.5(VCC) U52.1(OUT) U53.1(VCC) U57.5(VCC) ; also on sheet 7 14
5V0_AO_DLY: C230.1 U52.7(DELAY)
5V0_AO_EN: R338.2 R376.1 R385.1 U52.5(EN)
5V0_AO_FB: R380.2 R381.1 U52.2(FB_NC)
GND: C206.2 C207.2 C223.2 C224.2 C230.2 C231.2 C232.2 C233.2 C234.2 C235.2 C238.2 Q41.2(S) Q46.2(S) Q48.2(S) Q49.2(S) Q55.2(S) Q57.2(S) Q59.2(S) Q60.2(S) R376.2 R381.2 R389.2 R392.2 U42.4(GND) U48.3(GND) U52.4(GND) U52.9(TPAD) U53.12(GND) U57.3(GND) ; also on sheet 1 2 3 4 5 6 7 9 10 11 12 13 14 16 17 18 19 20 21 22 23 24 25 26 30
VDD_19V_IN: C223.1 R338.1 R377.1 R390.1 U52.8(IN) ; also on sheet 7
CARRIER_PWR_ON: Q41.1(G) ; also on sheet 4 6 14 30
CARRIER_PWR_ON_DLY: C206.1 Q41.3(D) Q55.1(G) R288.2
CARRIER_STBY: Q57.3(D) R291.2 U48.2(B)
MOD_PWR_CFG_9V: Q59.3(D) R385.2
MOD_PWR_CFG_9V*: Q46.3(D) Q59.1(G) R390.2 R392.1
MOD_PWR_CFG_ID: Q46.1(G) Q48.1(G) R377.2 R389.1 ; also on sheet 14 30
MOD_PWR_CFG_ID_L: Q56.1(G) ; also on sheet 14
MOD_PWR_ON_CLK: D37.3(C) R292.2 R386.2 U42.1(CP) U53.10(RST)
MOD_PWR_ON_RST: R290.2 U42.6(RD*) U57.4(OUT)
MOD_PWR_ON_SET: R378.2 U42.7(SD*)
MOD_PWR_ON_STATE: U42.5(Q) ; also on sheet 14
MOD_PWR_ON_STATE_L: U42.2(D) U42.3(Q*) ; also on sheet 14
MOD_VIN_EN: R290.1 U53.9(EN) U57.1(IN1) ; also on sheet 7 14
ONOFF_CTLR_INT: R289.2 R395.2 U48.1(A) U53.11(INT)
ONOFF_CTLR_INT_DLY: C224.1 Q48.3(D) Q49.3(D) Q60.1(G) R393.2
ONOFF_CTLR_INT_OR: Q49.1(G) U48.4(Y) U57.2(IN2)
ONOFF_CTLR_INT_OR_CPO_DLY: Q55.3(D) Q60.3(D) R276.1 R379.2
ONOFF_CTLR_PBOUT: R388.2 U53.8(PBOUT) ; also on sheet 14
ONOFF_CTLR_PSHOLD: R276.2 U52.3(PG) U53.4(PSHOLD)
ONOFF_CTLR_SR_DLY: C231.1 U53.5(CSRD)
ONOFF_CTLR_VCCLO_L: DS1.1(C) U53.7(VCCLO*)
ONOFF_CTLR_VCCLO_LED: DS1.2(A) R391.2
ONOFF_CTLR_VREF: C232.1 U53.3(VREF)
POWER_BTN: D36.3(C) D37.1(A) Q56.2(S) R275.1 R292.1 U53.6(PB*) ; also on sheet 1
POWER_BTN_2_SR: Q56.3(D) R275.2 R387.2 U53.2(SR*)
SNN_5V0_AO_NC: U52.6(NC)
SOC_PWR_REQ: Q57.1(G) ; also on sheet 5 12 30
WAKE_L: D36.1(A) R289.1 ; also on sheet 30

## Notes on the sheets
sheet 15
- A
- B
- C
- D
- E
- F
- G
- H
- No Stuff Rdiv
- for Fixed Output
- 1
- 1
- Enable at 8V or 4.5V Rising
- 2
- 2
- 3
- 3
- 4
- 4
- Weak Pull-Down on page 29
- 5
- 5
- NVIDIA CORPORATION
- 2701 SAN TOMAS EXPRESSWAY
- ASSEMBLY
- <ASSEMBLY_DESCRIPTION>
- SANTA CLARA, CA 95050, USA
- PAGE DETAIL
- ON OFF CONTROLLER
- NV_PN
- 600-82597-BASE-900
- ALL NVIDIA DESIGN SPECIFICATIONS, REFERENCE SPECIFICATIONS, REFERENCE BOARDS, FILES, DRAWINGS, DIAGNOSTICS, LISTS AND OTHER DOCUMENTS OR INFORMATION (TOGETHER AND SEPARATELY, 'MATERIALS') ARE BEING PROVIDED 'AS IS'. THE MATERIALS MAY
- CONTAIN KNOWN AND UNKNOWN VIOLATIONS OR DEVIATIONS OF INDUSTRY STANDARDS AND SPECIFICATIONS. NVIDIA MAKES NO WARRANTIES, EXPRESSED, IMPLIED, STATUTORY OR OTHERWISE WITH RESPECT TO THE MATERIALS OR OTHERWISE, AND EXPRESSLY DISCLAIMS ALL
- PCB REV
- P2597-C02
- PAGE
- 19 OF 34
- .
- IMPLIED WARRANTIES INCLUDING, WITHOUT LIMITATION, THE WARRANTIES OF DESIGN, OF NONINFRINGEMENT, MERCHANTABILITY OR FITNESS FOR A PARTICULAR PURPOSE, OR ARISING FROM A COURSE OF DEALING, TRADE USAGE, TRADE PRACTICE, OR INDUSTRY STANDARDS.
- BOM REV
- A
- DATE
- 23-OCT-2017
- A
- B
- C
- D
- E
- F
- G
- H
